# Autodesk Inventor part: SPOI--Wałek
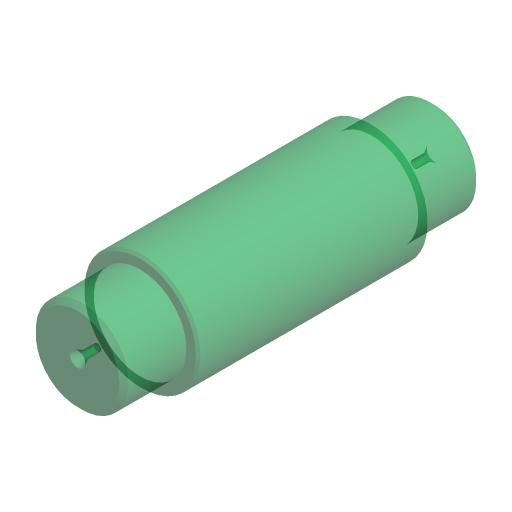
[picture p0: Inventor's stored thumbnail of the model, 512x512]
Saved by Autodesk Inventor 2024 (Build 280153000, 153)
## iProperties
Company: ATC
Shininess: 20.0
Length Units: 11269
Angle Units: 11279
Time Units: 11290
Mass Units: 11283
Length Display Precision: 3
Angle Display Precision: 2
Compacted: True
Created: 2023-03
Part Number: SPOI--Wałek
Document SubType Name: Modeling
Designer: Andrzej Jaskulski
Material: Kurs-AJ
Density: 1 g/cm^3
Mass: 32.9189 g
Surface Area: 65.2455 cm^2
Volume: 32.9189 cm^3
Appearance: Przezroczyste - zielone 1
Checked By: A.J.
Engr Approved By: Andrzej Jaskulski
Mfg Approved By: Andrzej Jaskulski
Authority: A.J.
Density: 0.0
Volumn: 0.0
Area: 0.0
PropertySet Name: Model Information
Control State: 0
Master: False
Checked Out: False
Title: A.J.: Kurs R2024-MEP
Author: Andrzej Jaskulski
Revision Number: 1/24
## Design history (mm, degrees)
workplane "Work Plane2"
node "Hole1" dims "d9" = 1.6, "d10" = 3.35, "d11" = 2, "d12" = 60 deg, "d13" = 4.3, "d14" = 120 deg, "d30" = 6
node "Mirror1"
node "Chamfer1" dims "d15" = 1, "d16" = 1, "d31" = 45 deg
node "Chamfer2" dims "d17" = 0.5, "d18" = 0.5, "d32" = 45 deg
node "Bryła1"
  node "Extrusion1" dims "d1" = 50, "d2" = 0
  node "Extrusion2" dims "d5" = 13.5, "d6" = 0
workaxis "Work Axis1"
node "Korpusy bryłowe"
node "Korpusy powierzchniowe"
sketch "Sketch1"
  geometry: C1 r 12.5 at (0, 0)
  constraints: 1 centre point
  dimensions: "d3" = 25 diameter of C1
sketch "Sketch2"
  geometry: C1 r 12.5 at (0, 0) reference; C2 r 10 at (0, 0)
  constraints: 1 centre point, 1 coincident
  dimensions: "d4" = 20 diameter of C2
sketch "Sketch3"
  geometry: C1 r 10 at (0, 0) reference; 1 further point
  constraints: 1 coincident
other parameters: "d8" = -25, "d24" = 45 (derived)
